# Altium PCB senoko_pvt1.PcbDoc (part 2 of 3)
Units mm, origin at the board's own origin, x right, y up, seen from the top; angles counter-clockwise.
Board outline 124.5 x 41 mm, 4 copper layers (Top Layer, Internal Plane 1, Internal Plane 2, Bottom Layer), stack 1.671 mm thick; 226 components, 139 nets, 1479 pads, 355 vias.
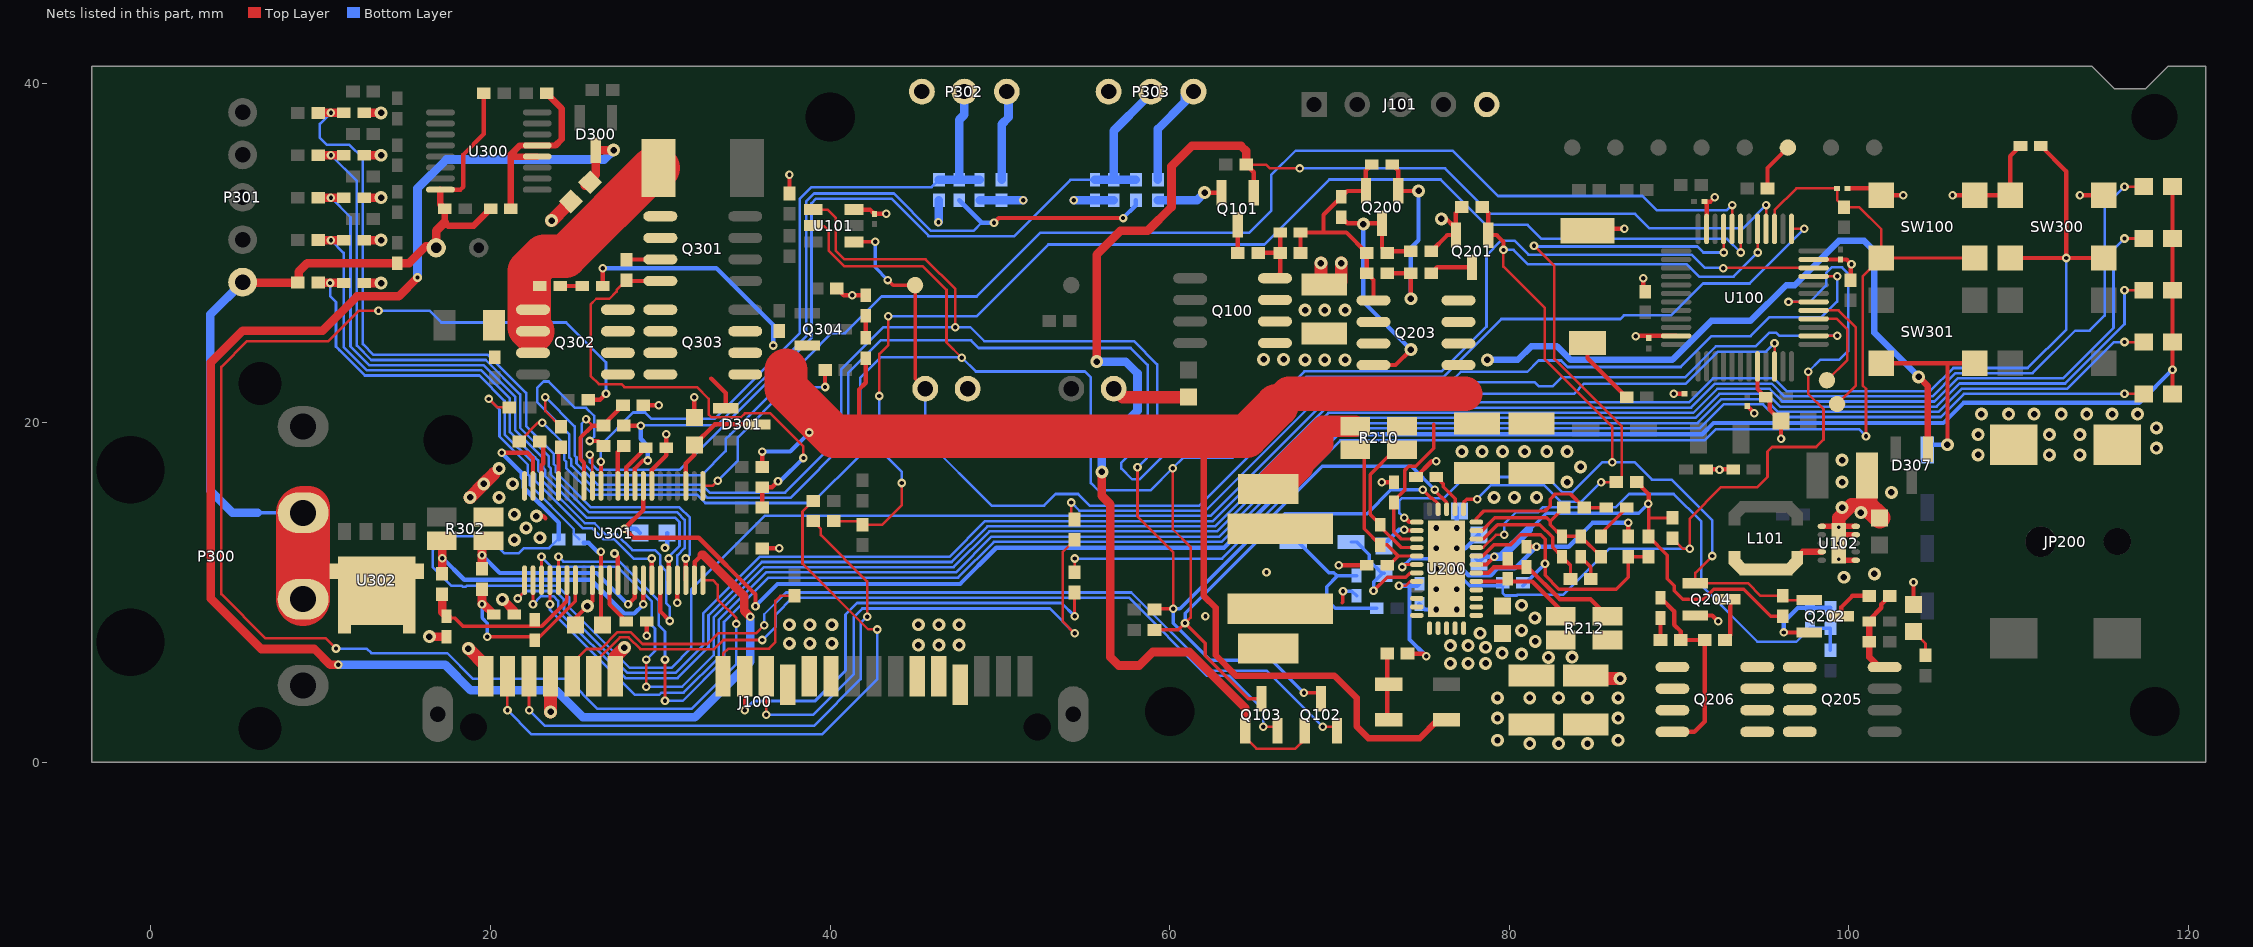
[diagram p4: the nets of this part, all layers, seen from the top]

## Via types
v1: diameter 0.508, hole 0.254, Top Layer to Bottom Layer, tented both sides, 187 vias
v2: diameter 0.762, hole 0.381, Top Layer to Bottom Layer, tented both sides, 155 vias
v3: diameter 0.66, hole 0.33, Top Layer to Bottom Layer, tented top, 9 vias
v4: diameter 0.5, hole 0.2, Top Layer to Bottom Layer, 3 vias
v5: diameter 0.66, hole 0.33, Top Layer to Bottom Layer, tented both sides, 1 vias

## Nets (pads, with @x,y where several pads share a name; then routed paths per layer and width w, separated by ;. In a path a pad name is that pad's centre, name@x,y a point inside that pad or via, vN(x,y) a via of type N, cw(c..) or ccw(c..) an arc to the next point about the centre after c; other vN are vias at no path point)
ADC_IN6: J104.1 U100.16 | length 5.7
  Top Layer w0.152: U100.16@97.917,26.114 99.286,26.114 99.9,25.5 99.9,23.7 J104.1@98.7,22.5
ADC_IN7: J105.1 U100.17 | length 7.9
  Top Layer w0.152: U100.17@97.917,26.614 99.386,26.614 100.4,25.6 100.4,22.2 J105.1@99.3,21.1
ANA_METER: J102.1 P101.1 U100.14 U101.1 | length 76.9
  Top Layer w0.152: U100.14@97.917,25.114 v1@99.297,25.114
  Top Layer w0.203: U101.1@41.4,30.65 v1(42.65,30.65) ; v1(43.4,28.4) 43.7,28.1 J102.1@45,28.1 45,22.6 P101.1@45.6,22
  Bottom Layer w0.152: P101.1@45,22 45.6,21.4 45.6,19.025 49.505,15.12 52.6,15.12 53.28,15.8 54.6,15.8 55.28,15.12 61.744,15.12 68.428,21.804 76.804,21.804 77.39,22.39 81.488,22.39 81.738,22.14 82.54,22.14 83.071,22.671 90.333,22.671 92.153,24.49 94.49,24.49 95.309,25.309 95.7,25.309 95.887,25.122 v1(99.305,25.122)
  Bottom Layer w0.203: v1(42.65,30.65) 42.65,29.15 v1(43.4,28.4)
BAT_PGND: C309.2 C310.2 C311.2 J301.1 P300.2 P300.3 P301.5 R317.1 R339.2 U300.8 U302.5 U302.6 U302.7 U302.8 U302.9 | length 54.6
  Top Layer w0.254: U302.9@13.3,10.103 15.205,8.198 U302.7@15.205,7.838 ; U300.8@17.05,33.725 18.225,33.725 18.4,33.9 18.4,35.8 19.6,37 R339.2@19.6,39.4
  Top Layer w0.381: U300.8@17.05,33.725 17.05,32.85 C309.2@17.3,32.6 17.3,31.8 17.5,31.6 19,31.6 C310.2@20,32.6
  Top Layer w0.508: P301.5@5.4,28.275 5.425,28.25 R317.1@8.65,28.25 8.7,28.3 8.7,28.9 9.2,29.4 C311.2@14.5,29.4 15.2,29.4 16.2,30.4 16.8,30.4 16.8,31.3 17.3,31.8 ; J301.1@17,30.3 J301.1@17,30.4
  Top Layer w2.54: P300.2@8.96,14.69 P300.2@9.27,15
  Top Layer w3.175: P300.3@8.96,9.61 P300.2@8.96,14.69
  Bottom Layer w0.178: P300.2@8.95,14.7 P300.2@8.96,14.69
  Bottom Layer w0.229: 6.3,14.7 P300.2@8.95,14.7
  Bottom Layer w0.508: P301.5@5.4,28.275 3.5,26.375 3.5,16 4.8,14.7 6.3,14.7
BAT_PROTECTED: C207.1 C208.1 C223.2 C301.1 C302.2 D200.1 D307.1 Q203.5 Q203.6 Q203.7 Q203.8 Q303.1 Q303.2 Q303.3 Q304.2 R210.3 R304.2 R319.1 U200.20 | length 145.2
  Top Layer w0.203: U200.20@74.55,13.15 73.631,13.15 73.2,13.581 C223.2@73.2,15.3 73.2,15.4 73.825,16.025 73.825,17.184 74.066,17.425 74.484,17.425 75.55,18.491 75.55,19.9
  Top Layer w0.254: C301.1@26.6,28.05 v1(26.6,29.1) ; R319.1@36,17.4 v1(36,18.3) ; 41.7,19.2 41.7,21.95 42.1,22.35 C302.2@42.1,23.8
  Top Layer w0.381: 63.175,19.2 62,18.025 62,9.8 62.7,9.1 62.7,6.3 63.9,5.1 69.7,5.1 71,3.8 71,2.125 71.7,1.425 74.725,1.425 75.8,2.5 D200.1@76.3,2.5 ; v2(104.1,22.7) 104.65,22.15 D307.1@104.65,18.45
  Top Layer w2.032: 66.3,21 67,21.7 77.4,21.7
  Top Layer w2.54: 37.4,23.1 37.4,22.029 40.229,19.2 41.7,19.2 63.175,19.2 64.5,19.2 66.3,21
  Bottom Layer w0.254: v1(26.6,29.1) 33.3,29.1 36.65,25.75 v1(36.65,24.55) ; v1(36,18.3) 37.65,18.3 v1(38.775,19.425)
  Bottom Layer w0.381: v2(78.7,23.7) 80.5,23.7 81.3,24.5 82.8,24.5 83.6,23.7 89.6,23.7 91.9,26 94.2,26 96.3,28.1 96.8,28.1 99.411,30.711 100.889,30.711 101.5,30.1 101.5,25.3 v2(104.1,22.7)
CHG_ACIN: C217.1 R214.2 R215.1 U200.9 | length 30
  Top Layer w0.152: U200.9@78.05,12.65 78.45,12.65 79.2,13.4 v1(79.7,13.4)
  Bottom Layer w0.152: v1(79.7,13.4) 79.7,14.05 80.375,14.725 81.675,14.725 81.975,15.025 86.275,15.025 87.05,15.8 89.675,15.8 91.3,14.175 91.3,10.4 94.6,7.1 96.9,7.1 C217.1@97.7,7.9
  Bottom Layer w0.203: C217.1@97.7,7.9 R215.1@98.9,7.9 R214.2@98.9,6.6
CHG_ACOK: Q201.1 Q202.1 Q204.1 R203.2 R222.2 U100.29 U200.18 | length 70.8
  Top Layer w0.152: v1(79.65,30.175) 79.65,29.2 82.075,26.775 82.075,23.75 86.05,19.775 v1(86.05,17.675) ; v1(91.95,12.15) 90.95,11.15 Q204.1@90.95,10.55 94.05,10.55 94.8,9.8 R222.2@96.1,9.8 96.35,9.55 Q202.1@97.65,9.55 ; v1@94.617,30.033 U100.29@94.617,31.414
  Top Layer w0.254: v1(73.8,14.4) 73.854,14.4 74.104,14.15 U200.18@74.55,14.15 ; R203.2@78.4,32.7 78.75,32.35 Q201.1@78.75,31.05 79.25,31.05 79.65,30.65 v1(79.65,30.175)
  Bottom Layer w0.152: v1(73.8,14.4) 73.525,14.675 73.525,15.425 73.65,15.55 76.125,15.55 77.375,16.8 82.225,16.8 83.135,15.89 83.69,15.89 85.475,17.675 v1(86.05,17.675) 87.368,17.675 88.4,16.642 89.557,16.642 91.95,14.25 v1(91.95,12.15) ; v1(79.65,30.175) 80.24,30.175 81.09,29.325 90.45,29.325 91.175,28.6 93.2,28.6 v1(94.625,30.025)
CHG_ALERT: R326.2 U100.25 | length 107.9
  Top Layer w0.152: U100.25@96.617,31.414 v1(97.361,31.414) v1@97.375,31.4
  Top Layer w0.254: v1(25.85,18.925) 26.35,18.925 R326.2@26.65,18.625
  Bottom Layer w0.152: v1(25.85,18.925) 26.108,19.183 26.108,20.4 25.632,20.875 24.975,20.875 23.425,22.425 23.125,22.425 22.742,22.042 22.742,21.208 24.645,19.305 24.645,17.94 24.754,17.831 24.754,17.47 26.174,16.05 32.3,16.05 32.776,15.574 37.652,15.574 41.075,18.997 41.075,22.947 42.973,24.845 48.3,24.845 48.745,24.4 57.7,24.4 58.7,23.4 58.7,19.2 57.15,17.65 57.15,17.3 57.791,16.659 58.216,16.659 59.786,18.23 63.561,18.23 68.049,22.718 76.137,22.718 79.524,26.105 86.53,26.105 86.75,26.325 89.529,26.325 91.404,28.2 94.148,28.2 v1(97.361,31.414)
CHG_CE: R220.2 U100.33 U200.13 | length 39.5
  Top Layer w0.152: v1(81.45,30.425) 82.65,29.225 82.65,23.75 86.625,19.775 86.625,16.825 R220.2@86.3,16.5 v1(85.4,16.5) ; U100.33@92.617,31.414 92.617,30.033 v1(92.625,30.025)
  Top Layer w0.203: U200.13@77.3,14.9 77.3,15.3 77.5,15.5 v1(78.1,15.5)
  Bottom Layer w0.152: v1(78.1,15.5) 78.925,16.325 82.025,16.325 83,15.35 84.25,15.35 v1(85.4,16.5) ; v1@81.525,30.375 91.075,30.375 91.425,30.025 v1(92.625,30.025)
CHG_CSON: C212.1 R210.4 U200.21 | length 8.4
  Top Layer w0.203: R210.4@73.675,18.4 73.256,18.4 71.806,16.95 71.806,14.594 C212.1@72.4,14 72.4,13.879 73.629,12.65 U200.21@74.55,12.65
CHG_CSOP: C212.2 C218.2 R210.1 U200.22 | length 9.5
  Top Layer w0.203: R210.1@70.925,18.4 71.45,17.875 71.45,13.75 C212.2@72.4,12.8 72.8,12.8 73.45,12.15 ; C218.2@72.8,11.5 73.45,12.15 ; U200.22@74.55,12.15 73.45,12.15
CHG_CSSN: C216.2 R212.4 U200.5 | length 6
  Top Layer w0.254: U200.5@78.05,10.65 81.35,10.65 83.025,8.975 R212.4@83.025,8.6
CHG_CSSP: C216.1 C219.1 R212.1 U200.6 | length 9.1
  Top Layer w0.254: U200.6@78.05,11.15 78.75,11.15 79.079,11.479 81.095,11.479 82.975,9.6 84.775,9.6 R212.1@85.775,8.6
CHG_EAI: C220.2 C221.2 R223.1 R224.1 U200.11 | length 9.9
  Top Layer w0.203: U200.11@78.05,13.65 78.25,13.65 78.3,13.7 78.35,13.7 78.4,13.65 79.15,14.4 82.2,14.4 82.4,14.2 ; R223.1@83.2,15 82.4,14.2 ; R224.1@85.4,12.1 C220.2@84.2,13.3 C221.2@83.1,13.3 82.4,14 82.4,14.2
CHG_EAO: C221.1 R219.2 U200.10 | length 8
  Top Layer w0.203: U200.10@78.05,13.15 78.45,13.15 79.3,14 81.8,14 82.546,13.254 82.546,12.654 C221.1@83.1,12.1 83.6,11.6 R219.2@83.6,10.8
CHG_FBO: C225.2 R223.2 U200.12 | length 9
  Top Layer w0.203: U200.12@78.05,14.15 78.05,14.35 78.5,14.8 82.1,14.8 82.4,15.1 82.4,15.5 82.7,15.8 83.6,15.8 R223.2@84.4,15 C225.2@85.7,15
CHG_ICOUT: R216.2 R218.2 U100.18 U200.23 | length 52.7
  Top Layer w0.152: R216.2@89.6,13.2 90.225,12.575 v1(90.625,12.575) 90.625,14.35 92.475,16.2 94.6,16.2 95.2,16.8 95.2,18.3 95.467,18.567 98.067,18.567 98.5,19 98.5,20.8 97.6,21.7 v1(97.6,23) ; v1@96.425,27.125 v1(96.436,27.114) U100.18@97.917,27.114
  Top Layer w0.203: v1(73.7,11.5) 73.85,11.65 U200.23@74.55,11.65
  Bottom Layer w0.152: R218.2@79.6,10.575 79.6,10.4 79.6,9.975 79.75,9.825 80.438,9.825 80.472,9.86 83.16,9.86 85.875,12.575 v1(90.625,12.575) ; v1(96.436,27.114) 97.689,27.114 98.65,28.075 98.65,28.825 98.975,29.15 99.6,29.15 99.95,28.8 99.95,24.225 99.425,23.7 98.3,23.7 v1(97.6,23)
  Bottom Layer w0.203: v1(73.7,11.5) 74.184,11.984 75.942,11.984 76.284,11.642 76.284,11.19 76.658,10.816 77.25,10.816 77.666,10.4 R218.2@79.6,10.4
CHG_ICREF: R217.2 R218.1 R221.1 U200.8 | length 16.6
  Top Layer w0.203: U200.8@78.05,12.15 78.432,12.15 79.082,12.8 80.041,12.8 80.641,13.4 81.844,13.4 82.108,13.137 82.108,11.006 82.918,10.196 86.296,10.196 87,10.9 R221.1@87,12.1 R217.2@88.2,12.1
  Bottom Layer w0.203: R218.1@80.8,10.4 v1(82.1,11.7)
CHG_IRQ: R115.1 U100.10 | length 48.2
  Top Layer w0.152: v1(54.2,15.3) 54.2,14.5 R115.1@54.4,14.3 ; U100.10@95.617,23.314 v1(95.617,24.683)
  Bottom Layer w0.152: v1(54.2,15.3) 54.685,14.815 62.115,14.815 68.799,21.499 76.999,21.499 77.2,21.7 83.8,21.7 84.4,22.3 90.393,22.3 92.279,24.186 95.119,24.186 v1(95.617,24.683)
CHG_MASTERPWR: Q101.1 Q102.1 Q103.1 R108.2 U100.28 | length 92.6
  Top Layer w0.152: Q103.1@64.45,1.85 64.45,1.45 65.1,0.8 67.4,0.8 67.95,1.35 Q102.1@67.95,1.85 ; R108.2@64.5,35.2 65.675,35.2 65.9,34.975 v1(67.65,34.975) ; U100.28@95.117,31.414 v1(95.117,32.817)
  Top Layer w0.254: R108.2@64.5,35.2 64.95,34.75 Q101.1@64.95,33.55
  Top Layer w0.508: v2(55.7,23.6) 55.7,29.9 57.1,31.3 58.7,31.3 60.1,32.7 60.1,35.1 61.3,36.3 64.2,36.3 64.5,36 R108.2@64.5,35.2 ; v2(56,17.1) 56,15.7 56.5,15.2 56.5,6.2 57,5.7 58.2,5.7 59,6.5 61.153,6.5 64.45,3.203 Q103.1@64.45,1.85
  Bottom Layer w0.152: v1(67.65,34.975) 76.222,34.975 78.897,32.3 87.397,32.3 88.247,31.45 93.75,31.45 v1(95.117,32.817)
  Bottom Layer w0.508: v2(55.7,23.6) 57.4,23.6 58.1,22.9 58.1,20.7 56,18.6 v2(56,17.1)
CHG_PWRSWITCH: C116.2 R119.1 R120.1 SW100.1 SW100.2 U100.27 | length 78.3
  Top Layer w0.152: R120.1@54.4,11.2 v1(54.4,12) ; U100.27@95.617,31.414 95.617,32.517 96.9,33.8 C116.2@99.3,33.8 99.3,33.1 R119.1@99.7,32.7 100.6,32.7 101.9,31.4 SW100.1@101.9,29.7 ; v1(101,19.2) 101,22 100.8,22.2 100.8,28.6 SW100.1@101.9,29.7 ; SW100.2@107.4,29.7 SW100.1@101.9,29.7
  Bottom Layer w0.152: v1(54.4,12) 63.083,12 70.042,18.959 91.502,18.959 92.167,19.624 100.576,19.624 v1(101,19.2)
CHG_SCL: Q103.3 R225.2 R329.2 U100.21 U101.5 U200.16 | length 153.9
  Top Layer w0.152: R329.2@21.7,18.9 22.8,20 v1(23.05,20) ; U101.5@39,31.6 38.95,31.6 38.925,31.575 39.625,31.575 39.925,31.275 39.925,30.119 40.819,29.225 45.45,29.225 46.85,27.825 46.85,24.725 v1(47.75,23.825) ; v1(60.175,17.325) 60.175,13.725 61.225,12.675 61.225,8.525 v1@61.063,8.363 ; U100.21@97.917,28.614 v1@99.297,28.614
  Top Layer w0.203: R225.2@59.1,7.8 60.5,7.8 v1(60.9,8.2) ; v1@61.063,8.363 v1(60.9,8.2) ; Q103.3@65.4,3.75 64.621,3.75 62.1,6.271 62.1,7 v1(60.9,8.2) ; v1(74.9,16.044) 75.39,15.554 75.467,15.554 75.8,15.221 U200.16@75.8,14.9
  Bottom Layer w0.152: v1(23.05,20) 23.05,20.025 24.34,18.735 24.34,17.814 24.45,17.705 24.45,17.344 26.048,15.745 32.174,15.745 32.65,15.269 38.941,15.269 41.78,18.108 41.78,22.655 42.975,23.85 47.75,23.85 48.584,23.016 55.007,23.016 55.35,22.673 55.35,16.45 55.788,16.013 58.863,16.013 v1(60.175,17.325) 60.775,17.925 63.687,17.925 68.176,22.413 76.551,22.413 77.138,23 81.057,23 81.721,23.664 83.043,23.664 83.426,23.281 90.081,23.281 91.9,25.1 94.2,25.1 95.312,26.213 98.387,26.213 99.305,27.13 v1(99.305,28.622)
  Bottom Layer w0.203: v1(60.9,8.2) 60.9,8.775 66.775,14.65 71.625,14.65 73.019,16.044 v1(74.9,16.044)
CHG_SDA: Q102.3 R226.2 R327.2 U100.22 U101.4 U200.15 | length 158.8
  Top Layer w0.152: v1(23.225,21.5) 23.225,20.675 R327.2@24.15,19.75 ; U101.4@39,32.55 39.85,32.55 40.325,32.075 40.325,30.15 40.85,29.625 45.625,29.625 47.375,27.875 v1(47.375,25.625) ; v1(58.1,17.375) 58.1,14.475 60.2,12.375 v1(60.2,9.05) ; v1(92.6,29.1) 92.614,29.114 96.514,29.114 U100.22@97.917,29.114
  Top Layer w0.203: R226.2@59.1,9 59.15,9.05 v1(60.2,9.05) ; v1(67.9,4.1) 68.8,4.1 68.9,4 Q102.3@68.9,3.75 ; v1(75.6,16.062) 75.6,16 76.3,15.3 U200.15@76.3,14.9
  Bottom Layer w0.152: v1(23.225,21.5) 24.95,19.775 24.95,18.066 25.059,17.957 25.059,17.596 26.301,16.355 32.426,16.355 32.902,15.879 37.354,15.879 40.649,19.174 40.649,23.124 43.15,25.625 48.25,25.625 49.075,24.8 57.9,24.8 59.26,23.44 59.26,18.535 ; v1(58.1,17.375) 59.26,18.535 ; v1(92.6,29.1) 92.586,29.114 91.511,29.114 90.725,29.9 81.125,29.9 80.3,30.725 79.518,30.725 78.65,29.857 78.65,25.662 76.011,23.023 67.923,23.023 63.435,18.535 59.26,18.535
  Bottom Layer w0.203: v1(67.9,4.1) 66,6 62.382,6 60.2,8.182 v1(60.2,9.05) 60.6,9.05 68.975,17.425 74.237,17.425 v1(75.6,16.062)
CHG_SYS: C100.1 C200.2 C201.1 C202.1 C209.1 C210.1 C211.1 Q100.1 Q100.2 Q100.3 Q200.2 Q203.1 Q203.2 Q203.3 R104.2 R200.1 R204.1 R212.3 U200.2 U200.3 U200.4 | length 16.5
  Top Layer w0.254: R104.2@67.7,30 C100.1@67.7,31.2 69.05,31.2 ; C200.2@71.9,35.2 71.55,34.85 Q200.2@71.55,33.65 70.45,33.65 C202.1@70.1,33.3 69.05,32.25 69.05,31.2 ; Q203.1@72,27.205 72,28.4 R200.1@71.6,28.8 R204.1@71.6,30 70.4,31.2 69.05,31.2
  Top Layer w0.762: C210.1@84.5,5.125 84.7,4.925 v2(86.525,4.925)
  other v2: 82.3,6.175 83.7,6.2 80.725,6.375 81.525,7.125 80.725,7.775 81.5,8.5 80.725,9.25 67.975,23.7 69.125,23.7 70.325,23.7 65.525,23.725 66.7,23.725 67.975,26.625 69.125,26.625 70.325,26.625
CHG_VREF: C214.1 R216.1 R217.1 R220.1 R222.1 U200.7 | length 28.9
  Top Layer w0.178: 88.2,14.3 88.3,14.4 R216.1@89.6,14.4
  Top Layer w0.203: v1@88.2,15.225 88.2,14.3 R217.1@88.2,13.3 89.3,12.2 89.3,10.8 89.7,10.4 89.7,10.1 90.2,9.6 91.441,9.6 92.041,10.2 93.8,10.2 95.4,8.6 R222.1@96.1,8.6
  Top Layer w0.254: U200.7@78.05,11.65 78.65,11.65 v1(79.1,12.1) ; R220.1@87.5,16.5 88.2,15.8 v1@88.2,15.225
  Bottom Layer w0.203: C214.1@78.016,11.984 C214.1@78.2,11.8 ; 81.315,13.814 82.176,14.675 87.625,14.675 v1(88.175,15.225)
  Bottom Layer w0.254: C214.1@78.2,11.8 78.5,12.1 v1(79.1,12.1)
  Bottom Layer w0.508: v1(79.1,12.1) 79.525,12.1 81.125,13.7
GG_2.5V: C321.1 R334.2 R338.1 U301.32 | length 17.5
  Top Layer w0.152: v1(19.9,21.4) 20.4,20.9 R338.1@21.1,20.9
  Top Layer w0.254: v1(26.5,12.4) U301.32@26.5,10.725 26.5,8.2 C321.1@26.6,8.1
  Bottom Layer w0.152: v1(19.9,21.4) 20.528,20.772 20.528,19.192 22.196,17.524 22.196,16.941 22.316,16.821 22.316,16.321 24.9,13.737 24.9,13.45 R334.2@25.225,13.125
  Bottom Layer w0.254: R334.2@25.475,12.925 25.775,12.925 26.3,12.4 v1(26.5,12.4)
GG_3.3V: C323.1 D302.1 D303.1 D304.1 D305.1 D306.1 U301.8 | length 115.5
  Top Layer w0.254: U301.8@29,16.3 29,14.875 v1(27.875,13.75) 28.4,13.225 32.266,13.225 35.6,9.891 v1(35.6,9.2) ; D302.1@119.05,21.7 D303.1@119.05,24.75 D304.1@119.05,27.8 D305.1@119.05,30.85 D306.1@119.05,33.9
  Bottom Layer w0.254: v1(27.875,13.75) 28.55,13.75 C323.1@28.8,13.5 ; v1(35.6,9.2) 36.9,10.5 47.652,10.5 49.783,12.631 63.189,12.631 69.873,19.315 91.355,19.315 92.02,19.98 105.557,19.98 106.744,21.167 117.092,21.167 v1(119.05,23.125)
GG_ALERT: R326.1 U301.11 | length 2.5
  Top Layer w0.254: U301.11@27.5,16.275 27.5,18.275 R326.1@27.85,18.625
GG_ASRN: R302.4 R325.2 U301.36 | length 13.1
  Top Layer w0.254: v1(28.1,9.3) 28.5,9.7 U301.36@28.5,10.725
  Top Layer w0.508: R302.4@19.375,13.05 19.5,12.925 R325.2@19.5,11.4
  Bottom Layer w0.254: v1(19.5,12.2) 20.546,11.154 26.246,11.154 v1(28.1,9.3)
GG_ASRP: R302.1 R328.2 U301.37 | length 16.8
  Top Layer w0.254: v1(29,9.3) U301.37@29,10.725
  Top Layer w0.508: R302.1@17.025,13.05 17.15,12.925 v1(17.15,12.013) R328.2@17.15,11.1
  Bottom Layer w0.254: v1@17.169,12.031 18.452,10.748 25.898,10.748 27.879,8.767 28.467,8.767 v1(29,9.3)
GG_CHG: R307.2 U301.44 | length 82
  Top Layer w0.152: v1(10.9,6.7) 10.3,7.3 6.759,7.3 4.15,9.909 4.15,23.291 5.659,24.8 10.45,24.8 12.25,26.6 v1(13.4,26.6) ; U301.44@32.5,10.725 33.1,10.725 33.375,10.45 33.375,9.6 34.475,8.5 v1(34.475,8.15)
  Top Layer w0.254: R307.2@25.75,21.35 26.45,21.35 v1(26.8,21.7)
  Bottom Layer w0.152: v1(10.9,6.7) 12.7,6.7 12.975,6.425 17.45,6.425 18.95,4.925 24.525,4.925 26.308,3.142 31.835,3.142 34.475,5.783 v1(34.475,8.15) ; v1(13.4,26.6) 16.4,26.6 17.1,25.9 24.45,25.9 26.8,23.55 v1(26.8,21.7)
GG_DISP: C326.1 R334.1 SW300.3 SW300.4 U301.21 | length 146.5
  Top Layer w0.254: v1(20.651,18.226) 22.174,18.226 22.5,17.9 U301.21@22.5,16.275 ; SW300.4@109.5,29.7 v1(112.8,29.7) ; C326.1@111.3,36.3 112.8,34.8 v1(112.8,29.7) ; SW300.3@115,29.7 v1(112.8,29.7)
  Bottom Layer w0.152: R334.1@23.987,13.162 23.44,12.615 21.975,12.615 21.66,12.3 20.825,12.3 19.8,13.325 17.425,13.325 16.6,12.5 16.6,11.48 17.688,10.392 18.305,10.392 18.358,10.34 18.547,10.34 18.599,10.392 23.952,10.392 24.632,9.712 24.632,9.132 28.197,5.567 30.642,5.567 31.825,6.75 31.825,10.195 36.14,14.511 62.411,14.511 68.665,20.765 69.094,21.194 90.576,21.194 91.991,22.61 95.578,22.61 96.328,21.86 104.779,21.86 106.143,23.224 110.524,23.224 112.8,25.5 v1(112.8,29.7)
  Bottom Layer w0.254: v1(20.651,18.226) 21.841,17.036 21.841,16.793 21.96,16.674 21.96,16.174 24.025,14.109 R334.1@24.025,13.125
GG_DSG: R308.2 U301.1 | length 11.4
  Top Layer w0.152: U301.1@32.5,16.275 33.075,16.275 v1(33.375,16.575)
  Top Layer w0.254: v1(39.7,22.1) R308.2@39.7,23.1
  Bottom Layer w0.152: v1(33.375,16.575) 34.563,17.763 34.563,19.138 37.525,22.1 v1(39.7,22.1)
GG_GSRN: C317.1 C318.1 R325.1 U301.29 | length 11.2
  Top Layer w0.203: v1(19.8,7.4) 22.903,7.4 25,9.497 U301.29@25,10.725
  Top Layer w0.508: v1(19.5,9.3) v1@19.6,9.3 ; R325.1@19.5,10.2 19.5,9.4 v1@19.6,9.3 ; C318.1@20.2,8.7 v1@19.6,9.3
  Bottom Layer w0.203: v1(19.5,9.3) 19.5,8.5 19.8,8.2 v1(19.8,7.4)
GG_GSRP: C317.2 C319.1 R328.1 U301.28 | length 10.6
  Top Layer w0.203: C319.1@17.5,8.5 17.9,8.5 18.4,8 23,8 24.5,9.5 U301.28@24.5,10.725
  Top Layer w0.508: R328.1@17.15,9.9 17.15,8.85 C319.1@17.5,8.5
GG_P1: C312.1 R313.2 U301.42 | length 46
  Top Layer w0.254: U301.42@31.5,10.725 v1(31.5,12)
  Top Layer w0.508: R313.2@9.85,38.25 v1(10.6,38.25) C312.1@11.15,38.25
  Bottom Layer w0.152: v1(10.6,38.25) 9.95,37.6 9.95,36.775 10.35,36.375 11.675,36.375 12.475,35.575 12.475,24.625 13.1,24 19.843,24 22.095,21.748 22.095,19.805 23.72,18.18 23.72,17.572 23.84,17.452 23.84,17.091 25.911,15.02 31.124,15.02 31.738,14.406 31.738,12.238 v1(31.5,12)
GG_P2: C315.1 R314.2 U301.41 | length 44.8
  Top Layer w0.254: v1(31,9.4) U301.41@31,10.725
  Top Layer w0.508: R314.2@9.85,35.75 v1(10.6,35.75) C315.1@11.15,35.75
  Bottom Layer w0.152: v1(10.6,35.75) 12.125,34.225 12.125,24.544 12.974,23.695 19.717,23.695 21.747,21.665 21.747,19.703 23.415,18.035 23.415,17.446 23.535,17.326 23.535,16.965 25.785,14.715 30.998,14.715 31.433,14.28 31.433,12.616 31,12.182 v1(31,9.4)
GG_P3: C313.1 R315.2 U301.40 | length 39.6
  Top Layer w0.254: U301.40@30.5,10.725 v1(30.5,12)
  Top Layer w0.508: R315.2@9.85,33.25 v1(10.6,33.25) C313.1@11.15,33.25
  Bottom Layer w0.152: v1(10.6,33.25) 11.75,32.1 11.75,24.488 12.847,23.39 19.591,23.39 21.443,21.538 21.443,19.57 23.111,17.903 23.111,17.319 23.23,17.2 23.23,16.839 25.658,14.411 30.872,14.411 31.129,14.154 31.129,12.742 30.5,12.114 v1(30.5,12)
GG_P4: C316.1 R316.2 U301.39 | length 40.1
  Top Layer w0.254: U301.39@30,10.725 30,8.875 v1(30.55,8.325)
  Top Layer w0.508: R316.2@9.85,30.75 v1(10.6,30.75) C316.1@11.15,30.75
  Bottom Layer w0.152: v1(10.6,30.75) 11.35,30 11.35,24.457 12.721,23.086 19.464,23.086 21.138,21.412 21.138,19.444 22.627,17.955 22.806,17.776 22.806,17.193 22.926,17.073 22.926,16.712 25.56,14.078 26.128,14.078 26.776,13.43 27.426,13.43 28.356,12.5 29.7,12.5 29.7,12.482 30,12.182 30,11.625 30.346,11.279 30.346,9.371 30.55,9.168 v1(30.55,8.325)
GG_P5: C314.1 R317.2 U301.38 | length 31.9
  Top Layer w0.254: U301.38@29.5,10.725 v1(29.5,12)
  Top Layer w0.508: R317.2@9.85,28.25 C314.1@11.15,28.25
  Bottom Layer w0.152: v1(10.55,28.225) 10.55,27.45 10.9,27.1 10.9,24.476 11.1,24.276 12.595,22.781 19.338,22.781 20.833,21.286 20.833,19.318 22.501,17.65 22.501,17.067 22.621,16.947 22.621,16.586 25.433,13.774 26.001,13.774 26.65,13.125 27.3,13.125 28.425,12 v1(29.5,12)
GG_SMBC: R329.1 U301.20 | length 2.7
  Top Layer w0.254: R329.1@22.9,18.9 23.1,18.7 23.1,17.6 23,17.5 U301.20@23,16.275
GG_SMBD: R327.1 U301.18 | length 2.4
  Top Layer w0.254: U301.18@24,16.275 R327.1@24,18.7
GG_SYSPRES: R324.2 R330.1 U100.32 U301.15 | length 90
  Top Layer w0.152: v1(25.625,20.2) 25.625,20.196 25.996,19.825 ; U100.32@93.117,31.414 v1(93.117,32.817) v1@93.125,32.825
  Top Layer w0.254: U301.15@25.5,16.275 25.5,17.65 25.293,17.857 25.293,19.122 25.996,19.825 R324.2@26.65,19.825 26.65,19.875 R330.1@27.8,21.025
  Bottom Layer w0.152: v1(25.625,20.2) 25.364,19.939 25.364,18.083 25.364,17.722 26.186,16.9 32.425,16.9 33.85,18.325 33.85,19.039 34.118,19.307 38.746,23.934 40.086,25.275 40.881,25.275 43.036,27.43 48.63,27.43 52.395,31.195 64.692,31.195 65.97,32.474 65.97,34.576 67.419,36.025 76.657,36.025 79.332,33.35 87.832,33.35 88.682,32.5 92.8,32.5 v1(93.117,32.817)
GG_TOUT: R324.1 R331.2 R332.2 U301.9 | length 48.3
  Top Layer w0.254: R324.1@27.85,19.825 v1(28.85,19.825) ; U301.9@28.5,16.275 28.5,17.3 28.975,17.775 v1(29.25,17.775) ; v1(49.65,31.775) 49.925,32.05 v1(57.25,32.05)
  Bottom Layer w0.152: v1@28.85,19.85 33.33,19.85 38.595,25.115 38.595,33.045 39.05,33.5 43.75,33.5 45.95,31.3 48.45,31.3 48.925,31.775
  Bottom Layer w0.254: v1(28.85,19.825) 28.85,19.05 29.25,18.65 v1(29.25,17.775) ; R331.2@47.6,33.1 48.925,31.775 v1(49.65,31.775) ; v1(57.25,32.05) 58,32.8 R332.2@58,33.1
GG_TS1: C325.1 P302.2 R331.1 R335.2 U301.13 | length 41.6
  Top Layer w0.254: U301.13@26.5,16.275 v1(26.5,17.7)
  Bottom Layer w0.152: v1(26.5,17.7) 26.5,18.7 28.4,20.6 29.1,20.6 29.475,20.225 29.75,20.225 33.175,20.225 38.22,25.27 38.22,33.201 38.895,33.875 45.975,33.875 R335.2@46.4,34.3
  Bottom Layer w0.508: R335.2@46.4,34.3 R331.1@47.6,34.3 ; P302.2@47.54,39.5 47.9,39.14 47.9,38.14 47.6,37.84 R331.1@47.6,34.3 ; C325.1@48.8,34.3 R331.1@47.6,34.3
GG_TS2: C324.1 P303.2 R332.1 R333.2 U301.14 | length 54.3
  Top Layer w0.152: v1(25.847,18.104) 26,17.95 U301.14@26,16.275
  Bottom Layer w0.152: v1(25.847,18.104) 25.847,17.671 26.3,17.217 31.129,17.217 33.668,19.757 38.9,24.989 38.9,32.919 39.176,33.195 43.624,33.195 45.775,31.044 45.775,30.975 50.825,30.975 54.15,34.3 C324.1@55.6,34.3
  Bottom Layer w0.508: C324.1@55.6,34.3 R332.1@58,34.3 ; R333.2@56.7,34.3 56.7,37.2 58.6,39.1 P303.2@58.6,39.5
GG_VCC: C307.1 D301.3 U301.3 | length 6.9
  Top Layer w0.254: U301.3@31.5,16.275 31.5,17.6 32,18.1 C307.1@32,18.7 33.2,19.9 D301.3@35.75,19.9
GND: C101.2 C102.2 C103.2 C104.2 C108.2 C109.2 C110.2 C111.2 C112.1 C113.1 C114.2 C115.2 C116.1 C117.2 C118.2 C201.2 C203.2 C207.2 C208.2 C209.2 C210.2 C211.2 C213.2 C214.2 C215.2 C217.2 C218.1 C219.2 C222.2 C223.1 C224.2 C303.2 C305.1 C307.2 C312.2 C313.2 C314.2 C315.2 C316.2 C318.2 C319.2 C320.2 C321.2 C322.2 C323.2 C324.2 C325.2 C326.2 J100.4 J100.5 J100.6 J100.10 J100.11 J100.12 J100.16 J100.19 J100.22 J101.5 JP200.2 JP200.3 P101.2 P102.2 P302.1 P303.1 Q101.2 Q201.2 Q202.2 Q204.2 R106.1 R114.1 R116.1 R118.2 R202.2 R203.1 R215.2 R221.2 R302.3 R311.2 R323.2 R330.2 R333.1 R335.1 R336.1 R337.1 SW100.3 SW100.4 SW300.1 SW300.2 TP107.1 U100.8 U100.23 U100.35 U100.47 U101.3 U102.1 U102.4 U102.5 U102.6 U102.11 U200.1 U200.19 U200.32 U200.33 U200.34 U200.35 U301.7 U301.22 U301.31 U301.34 | length 133.5
  Top Layer w0.254: v2(22.7,14.5) 23.1,14.5 23.233,14.367 ; C321.2@25,8.1 25,8.5 26,9.5 U301.31@26,10.725 ; v1(27.3,12.3) 27.5,12.1 U301.34@27.5,10.725 ; R330.2@29,21.025 v1(29.9,21.025) ; v1(29.2,7.45) C322.2@29.2,8.3 ; U301.7@29.5,16.275 29.5,17.225 30.35,18.075 C320.2@30.35,18.525 v1(30.35,19.325) ; C307.2@32,20.3 v1(32,21.5) ; R323.2@36,12.6 v1(37,12.6) ; R118.2@37.6,33.5 v1(37.6,34.6) ; R311.2@40.4,27.9 40.8,27.5 C305.1@42.1,27.5 ; U101.3@41.4,32.55 42.35,32.55 C115.2@42.6,32.3 v1(43.3,32.3) ; v2@62,33.6 v2(62.05,33.55) Q101.2@63.05,33.55 ; v1(69.95,11.6) C218.1@71.6,11.6 ; v1(72.475,16.5) C223.1@73.2,16.5 ; v1(73.8,13.7) 73.85,13.65 U200.19@74.55,13.65 ; C224.2@74.5,16.8 75.425,17.725 v1(75.7,17.725) ; R202.2@75.4,30.1 76.35,31.05 Q201.2@76.85,31.05 ; v2(76,32) 76.3,32 76.7,31.6 76.7,31.2 Q201.2@76.85,31.05 ; R203.1@77.2,32.7 76.85,32.35 Q201.2@76.85,31.05 ; C219.2@81,12.7 v1(81.6,12.7) ; C108.2@84.6,31.3 84.725,31.425 v1(86.775,31.425) ; R221.2@87,13.3 v1(87,14.1) ; v1(87.45,25.1) 87.464,25.114 U100.47@89.817,25.114 ; v1(87.875,28.5) 87.875,27.825 R106.1@88,27.7 ; v1@89.675,21.7 89.682,21.707 C109.2@90.314,21.707 ; Q204.2@90.95,8.65 91.95,8.65 v1(92.3,8.3) ; U100.35@91.617,31.414 91.617,32.883 C103.2@91.48,33.02 91.845,33.02 v1(92.1,33.275) ; C110.2@91.712,17.252 C111.2@93.057,17.252 ; C114.2@94.008,20.982 v1(94.425,20.565) v1@94.425,20.55 ; U100.8@94.617,23.314 94.617,21.983 C112.1@95.1,21.5 95.325,21.275 95.325,20.775 C113.1@96,20.1 v1(96,19.05) ; R114.1@95.2,33.8 95.2,35 TP107.1@96.4,36.2 ; v1(96.15,7.65) Q202.2@97.65,7.65 ; U100.23@97.917,29.614 99.861,29.614 v1(100.15,29.325) 100.1,29.275 R116.1@100.1,28.4 ; C116.1@99.9,33.8 101.5,33.8 SW100.3@101.9,33.4 v1(103.2,33.4) ; C213.2@103.8,9.3 v1(103.8,10.6) ; v1(106.1,33.4) SW100.4@107.4,33.4 SW300.2@109.5,33.4 109.5,35.7 C326.2@110.1,36.3 ; v1(113.6,33.4) SW300.1@115,33.4 SW300.1@114.7,33.7
  Top Layer w0.305: U102.6@98.4,13.9 99.4,13.9 U102.5@100.4,13.9 ; U102.11@99.3,13.4 99.4,13.4 U102.4@100.4,13.4 ; U102.11@99.4,11.9 U102.1@100.4,11.9
  Top Layer w0.508: C314.2@12.55,28.225 v2(13.55,28.225) ; C316.2@12.55,30.75 v2(13.55,30.75) ; C313.2@12.55,33.25 v2(13.55,33.25) ; C315.2@12.55,35.75 v2(13.55,35.75) ; C312.2@12.55,38.25 v2(13.55,38.25) ; v2(16.4,7.4) C319.2@17.4,7.4 ; v2(20.7,9.6) 21.4,8.9 C318.2@21.4,8.7
  Top Layer w0.762: v2(18.7,6.7) 19.725,5.675 J100.22@19.725,5.075 ; v2(18.8,15.6) v2(19.6,16.4) 20.2,17 ; v2(23.535,2.965) J100.19@23.535,5.075 ; v2(23.6,31.9) 24.434,32.734 C303.2@24.434,32.834 ; J100.16@27.345,5.075 27.345,6.219 v2(27.876,6.75) ; P102.2@56.74,22 57.24,21.5 C101.2@61.1,21.5 ; v2(68.9,29.4) 68.9,28.35 C201.2@69.1,28.15 69.95,28.15 70.1,28.3 v2(70.1,29.4)
  Top Layer w0.813: v4(99.4,12.9) 99.4,13.4 v4(99.4,13.85) 99.4,13.9 99.4,14.4 100.15,15.15 101.05,15.15
  Top Layer w1.27: C118.2@101.05,16.9 101.05,15.15 C117.2@101.8,14.4
  Bottom Layer w0.254: v1(30.275,12.625) 30.4,12.75 C323.2@30.4,13.5 ; C215.2@72.5,12.7 73.5,13.7 v1(73.8,13.7) ; C203.2@74.7,9.325 75.025,9 v3(75.7,9) ; v3(76.9,11.4) 77.205,11.4 77.584,11.021 78.9,11.021 79.305,11.425 80.325,11.425 v1(81.6,12.7) 83.5,12.7 84.9,14.1 v1(87,14.1) ; v3(76.9,12.6) 77.4,12.6 C214.2@78.2,13.4 ; v3(76.9,13.8) C222.2@76.9,15 ; v1(96.15,7.65) 96.15,8.25 97,9.1 C217.2@97.7,9.1 R215.2@98.9,9.1
  Bottom Layer w0.508: v1(46.375,31.8) 46.4,31.825 R335.1@46.4,33.1 ; C325.2@48.8,33.1 R336.1@50.1,33.1 v1(51.375,33.1) ; v1(54.35,33.1) C324.2@55.6,33.1 R333.1@56.7,33.1 ; R337.1@59.3,33.1 61.6,33.1 v2(62.05,33.55)
  other v1: 62.1,8.6 65.7,11.2 92.375,17.225 89.678,21.703 41.3,27.5
  other v2: 81.2,1.1 82.9,1.1 84.6,1.1 79.3,1.3 86.4,1.3 79.3,2.6 86.4,2.6 79.3,3.8 81.2,3.8 82.9,3.8 84.6,3.8 86.4,3.8 76.525,5.825 77.575,5.825 78.6,5.825 79.575,6.425 78.6,6.775 76.525,6.875 77.575,6.875 45.2,6.9 46.4,6.9 47.6,6.9 37.6,7 38.8,7 40.1,7 78.275,7.6 37.6,8.1 38.8,8.1 40.1,8.1 45.2,8.1 46.4,8.1 47.6,8.1 25.7,9.2 99.7,10.9 101.5,11.1 21.4,13.1 22.9,13.225 22.1,13.8 21.4,14.6 100.7,14.7 99.6,15 20.5,15.6 79.1,15.6 80.3,15.6 81.6,15.6 102.5,15.9 21.3,16.4 83.4,16.5 99.6,16.5 20.5,17.3 84.2,17.4 99.6,17.8 107.6,18.1 111.8,18.1 113.6,18.1 77.2,18.3 78.4,18.3 79.6,18.3 80.9,18.3 82.2,18.3 83.4,18.3 118.1,18.5 107.6,19.3 111.8,19.3 113.6,19.3 118.1,19.7 107.8,20.5 109.4,20.5 110.9,20.5 112.5,20.5 114,20.5 115.5,20.5 117,20.5
  other v3: 76.9,9 75.7,10.2 76.9,10.2 75.7,11.4 75.7,12.6
  other v4: 99.4,11.95
  other v5: 75.7,13.8
HOST_SMB_SCL: J100.17 Q103.2 | length 47.4
  Top Layer w0.152: J100.17@26.075,5.075 26.075,5.811 27.624,7.36 28.129,7.36 28.826,6.663 33.163,6.663 33.705,7.205 v1(36.005,7.205) ; v1(65.5,2.1) 66.1,2.1 Q103.2@66.35,1.85
  Bottom Layer w0.152: v1(36.005,7.205) 36.8,8 36.8,8.7 37.795,9.695 57.605,9.695 62.205,5.095 63.505,5.095 65.5,3.1 v1(65.5,2.1)
HOST_SMB_SDA: J100.18 Q102.2 | length 51.9
  Top Layer w0.152: J100.18@24.805,5.075 24.805,5.83 25.65,6.675 26.498,6.675 27.488,7.665 28.255,7.665 28.952,6.967 32.767,6.967 33.4,7.6 35.638,7.6 v1(36.119,8.081) ; v1(69,2.1) 69.6,2.1 Q102.2@69.85,1.85
  Bottom Layer w0.152: v1(36.119,8.081) 36.119,8.719 37.4,10 57.731,10 62.331,5.4 65.7,5.4 v1(69,2.1)
HOST_TO_PM_UART: R101.1 R109.1 U100.31 | length 73.2
  Top Layer w0.152: R101.1@40.2,14.2 41.7,14.2 R109.1@41.9,14 43.075,14 44.225,15.15 v1(44.225,16.45) ; v1(42.9,21.575) 42.9,24.05 43.425,24.575 v1(43.425,26.275) ; v1@93.617,30.033 U100.31@93.617,31.414
  Bottom Layer w0.152: v1(42.9,21.575) 42.9,18.425 44.225,17.1 v1(44.225,16.45) ; v1(43.425,26.275) 43.433,26.267 48.62,26.267 52.848,30.495 65.57,30.495 69.4,34.325 75.953,34.325 78.628,31.65 81.075,31.65 81.9,30.825 92.825,30.825 v1(93.625,30.025)
LED1: D306.2 U301.23 | length 116.9
  Top Layer w0.152: v1(21.6,9.65) 22,10.05 U301.23@22,10.725 ; v1@116.2,33.925 v1(116.225,33.9) D306.2@117.35,33.9
  Bottom Layer w0.152: v1(21.6,9.65) 22.037,10.087 23.826,10.087 24.325,9.589 24.325,9.009 28.071,5.263 30.888,5.263 32.531,6.906 32.531,8.781 35.85,12.1 47.025,12.1 49.131,14.206 62.537,14.206 68.97,20.639 69.22,20.889 90.702,20.889 92.118,22.305 95.451,22.305 96.201,21.555 104.905,21.555 106.269,22.919 110.819,22.919 113.325,25.425 114.175,25.425 115.05,26.3 115.05,32.725 v1(116.225,33.9)
LED2: D305.2 U301.24 | length 114
  Top Layer w0.152: v1(22.5,9.3) U301.24@22.5,10.725 ; v1(116.225,30.85) D305.2@117.35,30.85
  Bottom Layer w0.152: v1(22.5,9.3) 22.983,9.783 23.7,9.783 23.983,9.5 23.983,8.92 27.945,4.958 31.014,4.958 32.836,6.78 32.836,8.655 35.976,11.795 47.151,11.795 49.257,13.901 62.663,13.901 69.347,20.585 90.829,20.585 92.244,22 95.325,22 96.075,21.25 105.031,21.25 106.395,22.614 112.602,22.614 115.575,25.587 115.575,30.2 v1(116.225,30.85)
LED3: D304.2 U301.25 | length 115.2
  Top Layer w0.152: U301.25@23,10.725 v1(23,12.1) ; v1(29.175,6.05) v1(29.176,4.45) v1(29.176,4.45) ; v1(116.225,27.8) D304.2@117.35,27.8
  Bottom Layer w0.152: v1(23,12.1) 23.59,11.51 27.473,11.51 29.5,9.482 29.5,8.05 29.683,7.867 29.683,6.558 v1(29.175,6.05) ; v1(29.176,4.45) 31.286,4.45 33.14,6.305 33.14,8.528 36.102,11.49 47.278,11.49 49.383,13.596 62.789,13.596 69.223,20.029 69.473,20.28 90.955,20.28 92.37,21.695 92.623,21.695 95.199,21.695 95.949,20.945 105.157,20.945 106.522,22.31 112.729,22.31 116.225,25.806 v1(116.225,27.8)
LED4: D303.2 U301.26 | length 108.2
  Top Layer w0.152: v1(23.5,9.3) U301.26@23.5,10.725 ; v1(116.225,24.75) D303.2@117.35,24.75
  Bottom Layer w0.152: v1(23.5,9.3) 23.5,8.971 28.504,3.968 29.935,3.968 30.075,4.108 31.375,4.108 33.445,6.178 33.445,8.402 36.229,11.186 47.404,11.186 49.51,13.291 62.916,13.291 69.599,19.975 91.081,19.975 92.496,21.39 95.073,21.39 95.823,20.64 105.284,20.64 106.648,22.005 112.855,22.005 115.6,24.75 v1(116.225,24.75)
LED5: D302.2 U301.27 | length 110.9
  Top Layer w0.152: U301.27@24,10.725 v1(24,12.1) ; v1(30.275,3.625) v1(30.275,6.05) ; v1(116.225,21.7) D302.2@117.35,21.7
  Bottom Layer w0.152: v1(24,12.1) 24.285,11.815 27.599,11.815 29.898,9.515 29.898,8.083 30.275,7.706 v1(30.275,6.05) ; v1(30.275,3.625) 31.323,3.625 33.75,6.052 33.75,8.275 36.356,10.881 47.53,10.881 49.636,12.987 63.042,12.987 69.725,19.67 91.207,19.67 92.623,21.086 94.946,21.086 95.696,20.336 105.41,20.336 106.774,21.7 v1(116.225,21.7)
NetC100_2: C100.2 Q100.4 R104.1 R105.2 | length 4.1
  Top Layer w0.254: R105.2@65.2,30 R104.1@66.5,30 ; Q100.4@66.2,28.505 66.5,28.805 R104.1@66.5,30 ; C100.2@66.5,31.2 R104.1@66.5,30
NetC108_1: C108.1 R107.1 | length 4.2
  Top Layer w0.254: C108.1@84.6,24.7 84.6,23.8 R107.1@86.9,21.5
NetC200_1: C200.1 Q200.1 R200.2 R201.1 | length 12.4
  Top Layer w0.254: R200.2@72.8,28.8 R201.1@74.2,28.8 v2(74.2,27.3) ; C200.1@73.1,35.2 73.45,34.85 Q200.1@73.45,33.65 v2(74.65,33.65) v2@74.7,33.6
  Bottom Layer w0.254: v2(74.2,27.3) 74.2,30.3 74.65,30.75 v2(74.65,33.65)
NetC202_2: C202.2 Q200.3 Q203.4 R202.1 R204.2 | length 17
  Top Layer w0.254: C202.2@70.1,32.1 70.45,31.75 Q200.3@72.5,31.75 72.5,30.3 R204.2@72.8,30 72.9,30.1 R202.1@74.2,30.1 ; Q203.4@72,23.395 73.295,23.395 v2(74.2,24.3)
  Bottom Layer w0.254: v2(71.4,31.7) 71.4,27.1 v2(74.2,24.3)
NetC203_1: C203.1 R207.2 U200.25 | length 8.1
  Top Layer w0.152: v1(73.5,10.4) 73.9,10.4 74.15,10.65 U200.25@74.55,10.65
  Top Layer w0.254: R207.2@74,6.4 74.95,6.4 v1(75.1,6.25)
  Bottom Layer w0.254: v1(73.5,10.4) 74.075,10.4 ; C203.1@74.7,10.525 74.575,10.4 74.075,10.4 ; v1(75.1,6.25) 74.121,7.229 74.121,10.354 74.075,10.4
NetC204_1: C204.1 Q205.4 R205.1 R208.2 | length 5.2
  Top Layer w0.254: C204.1@101.2,8.3 101.2,8.4 101.9,9.1 101.9,9.3 R205.1@102.4,9.8
  Top Layer w0.381: C204.1@101.2,8.3 101.2,6.2 101.795,5.605 Q205.4@102.1,5.605
NetC205_1: C205.1 Q206.4 R206.2 R209.2 | length 11.3
  Top Layer w0.254: C205.1@88.9,9.7 89.7,8.9 89.7,8.1 90.1,7.7 R209.2@90.1,7.2 R206.2@91.5,7.2 91.5,2.4 90.895,1.795 Q206.4@89.6,1.795
NetC205_2: C205.2 Q206.1 Q206.2 Q206.3 R209.1 R212.2 | length 1.2
  Top Layer w0.254: R209.1@88.9,7.2 C205.2@88.9,8.4
NetC206_1: C206.1 D202.2 R211.2 | length 9.4
  Bottom Layer w0.203: D202.2@67.275,12.975 67.575,12.975 69.375,11.175 69.657,11.175 69.832,11 69.9,11 ; C206.1@71,11 69.9,11 ; R211.2@72.2,9.075 69.75,9.075 69.25,9.575 69.25,10.35 69.9,11
NetC206_2: C206.2 L200.1 L200B.1 U200.27 U200.28 U200.29 U200.30 U200.31 | length 1.6
  Top Layer w0.203: 70.15,9.4 70.2,9.45 v1(70.2,10.075)
  Bottom Layer w0.203: v1(70.2,10.075) 70.725,10.075 C206.2@71,9.8
NetC213_1: C213.1 R213.2 | length 1.7
  Top Layer w0.178: C213.1@103.8,7.7 104.5,7 R213.2@104.5,6.3
NetC215_1: C215.1 D202.1 U200.24 | length 7.1
  Top Layer w0.203: v1(72,10.1) 72.808,10.908 73.908,10.908 74.15,11.15 U200.24@74.55,11.15
  Bottom Layer w0.203: D202.1@70.675,12.975 71,12.975 71.75,12.225 71.75,11.875 72.5,11.125 C215.1@72.625,11.125 ; v1(72,10.1) 72,10.6 C215.1@72.5,11.1
NetC220_1: C220.1 R219.1 | length 1.5
  Top Layer w0.203: C220.1@84.2,12.1 84.8,11.5 R219.1@84.8,10.8
NetC224_1: C224.1 U200.14 | length 2.4
  Top Layer w0.203: C224.1@75.7,16.8 76.108,16.392 76.108,16.224 76.8,15.532 U200.14@76.8,14.9
NetC225_1: C225.1 R224.2 | length 2.3
  Top Layer w0.203: R224.2@85.4,13.3 85.4,13.5 C225.1@86.9,15
NetC300_1: C300.1 C301.2 | length 1.3
  Top Layer w0.254: C300.1@24.1,28.05 C301.2@25.4,28.05
NetC300_2: C300.2 F300.2 Q302.1 Q302.2 Q302.3 R300.2 R303.1 | length 13.8
  Top Layer w2.54: Q302.2@22.5,25.385 22.278,25.607 22.278,28.939 23.138,29.8 24.4,29.8 29.6,35 R300.2@29.9,35
NetC302_1: C302.1 C305.2 | length 1.3
  Top Layer w0.254: C302.1@42.1,25 C305.2@42.1,26.3
NetC303_1: C303.1 D300.3 U301.43 | length 94.5
  Top Layer w0.254: U301.43@32,10.725 32.033,10.758 32.033,11.808 32.45,12.225
  Top Layer w0.508: v1(11.025,5.75) 10.55,5.75 9.625,6.675 6.5,6.675 3.525,9.65 3.525,23.55 5.4,25.425 10.125,25.425 12.138,27.438 14.588,27.438 v1(15.7,28.55) ; C303.1@25.566,33.966 26.2,34.6 D300.3@26.2,36.05 v2(27.25,36.05) ; 32.45,12.225 32.512,12.225 34.94,9.797 34.94,8.926 v1(35.3,8.566)
  Bottom Layer w0.508: v1(11.025,5.75) 17.325,5.75 18.825,4.25 23.85,4.25 25.44,2.66 32.035,2.66 35.3,5.925 v1(35.3,8.566) ; v1(15.7,28.55) 15.7,33.8 17.4,35.5 26.7,35.5 v2(27.25,36.05)
NetC310_1: C310.1 R309.2 U300.12 U300.13 | length 11.2
  Top Layer w0.381: C310.1@21.2,32.6 21.2,35.8 ; U300.12@22.75,35.675 21.325,35.675 21.2,35.8 ; R309.2@23.3,39.4 24.2,38.5 24.2,36.7 23.825,36.325 U300.13@22.75,36.325 21.725,36.325 21.2,35.8
NetC320_1: C320.1 U301.10 | length 2.7
  Top Layer w0.254: U301.10@28,16.275 28,17.375 C320.1@29.15,18.525
NetC322_1: C322.1 U301.33 | length 2.8
  Top Layer w0.254: U301.33@27,10.725 27,9.3 C322.1@28,8.3
NetD200_2: D200.2 D201.2 R207.1 | length 3.9
  Top Layer w0.254: R207.1@72.8,6.4 72.8,2.6 D200.2@72.9,2.5
NetD301_1: D301.1 Q301.1 Q301.2 Q301.3 Q302.5 Q302.6 Q302.7 Q302.8 Q303.5 Q303.6 Q303.7 Q303.8 R301.2 | length 4.1
  Top Layer w0.254: R301.2@28,29.6 28.015,29.615 Q301.3@30,29.615 ; 33,22.6 33.85,21.75 D301.1@33.85,20.85
NetD308_1: D308.1 SW301.3 SW301.4 | length 11.6
  Top Layer w0.254: SW301.4@101.9,23.5 105.8,23.5 ; v2(105.8,18.7) 105.8,23.5 ; SW301.3@107.4,23.5 105.8,23.5
  Bottom Layer w0.254: D308.1@104.6,18.4 104.9,18.7 v2(105.8,18.7)
NetJ100_13: J100.13 R115.2 | length 31.7
  Top Layer w0.152: v1(36.235,2.8) J100.13@36.235,5.075 ; v1(54.4,7.6) 53.7,8.3 53.7,12.4 R115.2@54.4,13.1
  Bottom Layer w0.152: v1(36.235,2.8) 39,2.8 41.4,5.2 41.4,8.56 41.9,9.06 52.94,9.06 v1(54.4,7.6)
NetJ100_14: J100.14 R120.2 | length 27.7
  Top Layer w0.178: v1(34.965,3.065) J100.14@34.965,5.075 ; v1(54.4,8.6) R120.2@54.4,10
  Bottom Layer w0.178: v1(34.965,3.065) 35.5,3.6 39.1,3.6 40.9,5.4 40.9,8.7 41.578,9.378 53.622,9.378 v1(54.4,8.6)
NetJ100_15: J100.15 R103.2 | length 8.4
  Top Layer w0.152: J100.15@33.695,5.075 33.695,6.395 34,6.7 36.4,6.7 36.771,7.071 36.771,9.5 37.071,9.8 R103.2@37.9,9.8
NetJ100_20: J100.20 R101.2 | length 33.8
  Top Layer w0.152: J100.20@22.265,5.075 22.265,3.085 v1(22.275,3.075) ; R101.2@39,14.2 39.45,13.75 39.45,13.375 42.175,10.65 v1(42.175,8.575)
  Bottom Layer w0.152: v1(22.275,3.075) 23.2,2.15 39.05,2.15 41.8,4.9 41.8,8.2 v1(42.175,8.575)
NetJ100_21: J100.21 R100.2 | length 38.6
  Top Layer w0.152: J100.21@20.995,5.075 20.995,3.08 v1(21,3.075) ; R100.2@39,15.4 38.371,14.771 38.371,11.696 42.243,7.825 v1(42.775,7.825)
  Bottom Layer w0.152: v1(21,3.075) 22.425,1.65 39.525,1.65 42.775,4.9 v1(42.775,7.825)
NetL101_1: L101.1 U102.9 | length 1.6
  Top Layer w0.381: L101.1@96.95,12.075 97.275,12.4 U102.9@98.4,12.4
NetL200_2: L200.2 L200B.2 R210.2 | length 14.1
  Top Layer w0.254: L200.2@65.8,16.1 66.6,16.9 66.6,17.4
  Top Layer w1.27: L200.2@65.8,16.1 65.8,16.6 66.6,17.4 69,19.8 ; L200.2@66.6,16.9 66.6,16.1 67.8,17.3 67.8,17.5 69,18.7 69,19.8 ; R210.2@70.925,19.8 69,19.8
NetP302_3: P302.3 R336.2 | length 5.5
  Bottom Layer w0.508: P302.3@50.08,39.5 50.5,39.08 50.5,37.98 50.1,37.58 R336.2@50.1,34.3
NetP303_3: P303.3 R337.2 | length 5.7
  Bottom Layer w0.508: R337.2@59.3,34.3 59.3,37.3 60.9,38.9 P303.3@60.9,39.3
NetQ101_3: Q101.3 R105.1 | length 1.6
  Top Layer w0.254: R105.1@64,30 Q101.3@64,31.65
NetQ201_3: Q201.3 R201.2 | length 2.5
  Top Layer w0.254: R201.2@75.4,28.8 75.75,29.15 Q201.3@77.8,29.15
NetQ202_3: Q202.3 R205.2 | length 2.5
  Top Layer w0.254: Q202.3@99.55,8.6 99.55,9.15 100.2,9.8 R205.2@101.2,9.8
NetQ204_3: Q204.3 R206.1 | length 2.7
  Top Layer w0.254: R206.1@92.6,7.3 R206.1@92.7,7.2 93,7.5 93,9.45 Q204.3@92.85,9.6
NetQ205_5: Q205.5 Q205.6 Q205.7 Q205.8 Q206.5 Q206.6 Q206.7 Q206.8
NetQ301_4: Q301.4 R301.1 R320.1 R321.1 | length 29
  Top Layer w0.152: R301.1@28,28.4 27.425,27.825 27.425,27.725 27,27.3 26.225,27.3 25.9,26.975 25.9,22.75 26.375,22.275 27.702,22.275 27.877,22.1 32.15,22.1 32.85,21.4 32.85,20.477 33.005,20.321 34.746,20.321 34.975,20.55 36.473,20.55 38.425,18.598 v1(38.425,17.925)
  Top Layer w0.254: R301.1@28,28.4 28.055,28.345 Q301.4@30,28.345 ; R321.1@36,15 R320.1@36,16.2 36.575,16.2 v1(36.925,16.55)
  Bottom Layer w0.254: v1(36.925,16.55) 37.05,16.55 v1(38.425,17.925)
